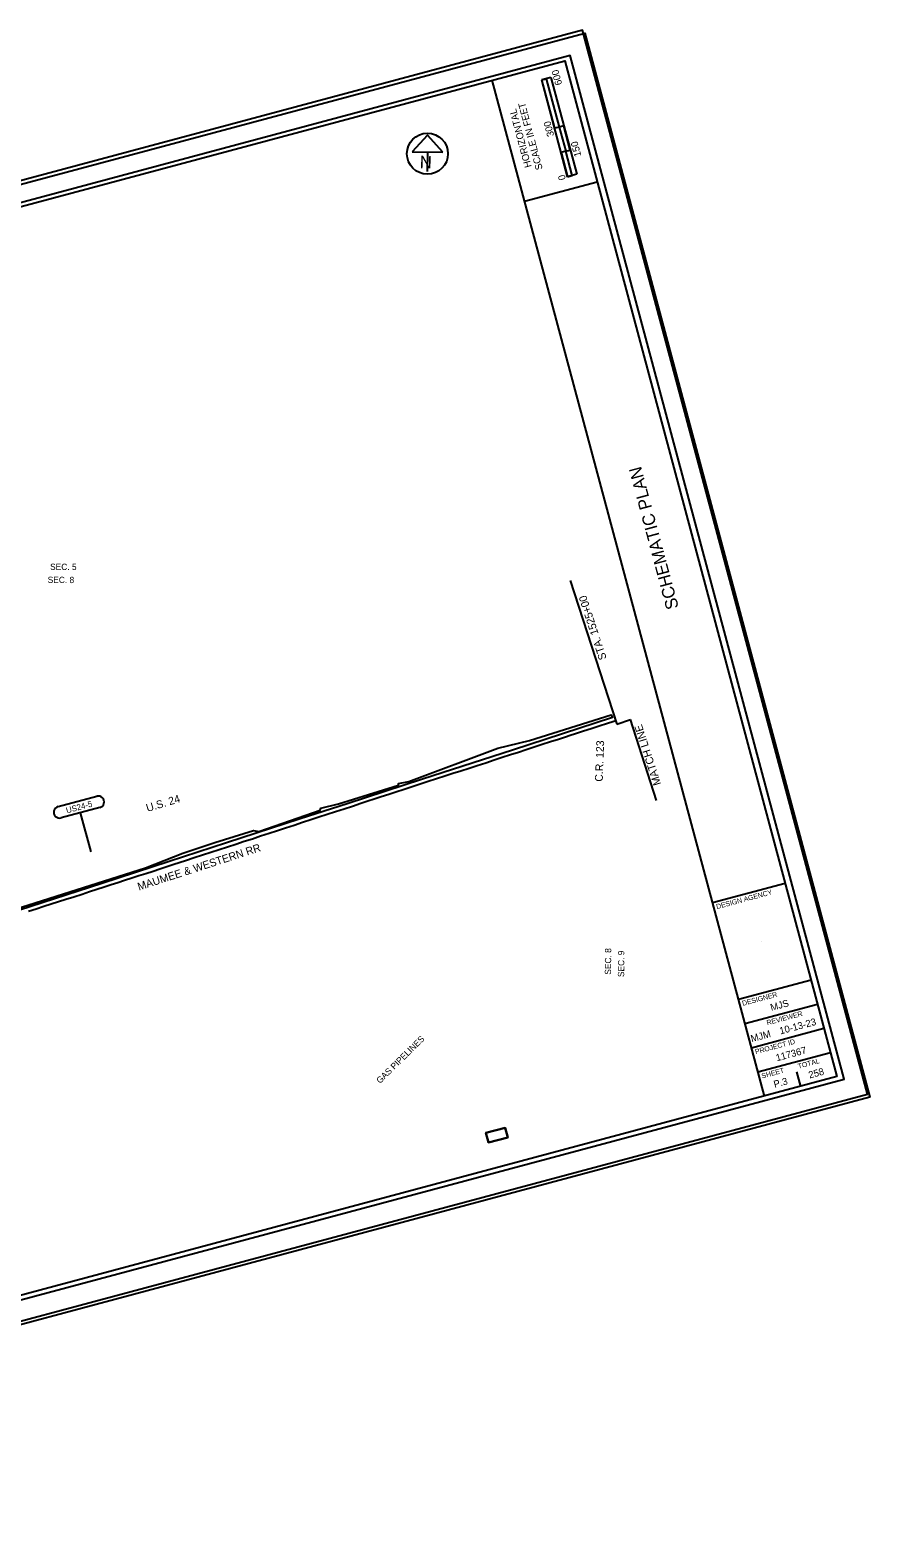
# Model space of a CAD drawing. Extents: x -361782439 to 1410642, y -263199455 to 583641.
# Drawn here: x 1405611 to 1410642, y 573245 to 582277 of the extents above; entities that cross this region are included whole.
import ezdxf

# ---------------------------------------------------------------- set-up
doc = ezdxf.new("R2010")
doc.units = 0
for name, color, linetype in [('HY_X_Wetland_Area', 7, 'Continuous'), ('Level 63', 7, 'Continuous'), ('RD_X_RR_1', 7, 'Continuous'), ('SH_Border', 7, 'Continuous'), ('SH_Cut_Line', 7, 'Continuous'), ('SH_Data', 7, 'Continuous'), ('SH_Masking', 7, 'Continuous'), ('SH_Text', 7, 'Continuous'), ('UT_X_Gas', 7, 'Continuous')]:
    doc.layers.add(name, color=color, linetype=linetype)

msp = doc.modelspace()

# ---------------------------------------------------------------- linework, layer by layer
at = {"layer": 'HY_X_Wetland_Area'}
msp.add_lwpolyline([(1404814.3, 576788.2), (1406301.7, 577259.9), (1406525.2, 577347.2), (1406717.1, 577411.1), (1406950.3, 577483.5), (1406982, 577477.5), (1407349, 577603.6), (1407353.2, 577617.4), (1407457.8, 577642.5), (1407818.3, 577753.7), (1407817.8, 577764.5), (1407879.3, 577776.4), (1407879.3, 577776.4), (1407879.3, 577776.4), (1408413.7, 577975.5), (1408603.3, 578020.9), (1409091.1, 578175.2), (1409100.6, 578159), (1408500.2, 577964.2), (1407961.4, 577789.4), (1407509.6, 577642.8), (1407229.4, 577552), (1406965.2, 577466.2), (1406787.2, 577408.5), (1406444.9, 577297.4), (1406444.9, 577297.4), (1406444.9, 577297.4), (1406040.1, 577166.1), (1404694.7, 576729.6)], dxfattribs=at)
for points in [[(1408341.6, 575671.3), (1408341.6, 575671.3), (1408341.6, 575671.3), (1408341.6, 575671.3), (1408341.6, 575671.3), (1408341.6, 575671.3), (1408457.5, 575702.4), (1408457.5, 575702.4), (1408473, 575644.4), (1408473, 575644.4), (1408473, 575644.4), (1408357.1, 575613.4), (1408357.1, 575613.4), (1408357.1, 575613.4), (1408357.1, 575613.4), (1408357.1, 575613.4), (1408357.1, 575613.4), (1408357.1, 575613.4), (1408357.1, 575613.4), (1408357.1, 575613.4), (1408341.6, 575671.3), (1408341.6, 575671.3)], [(1408341.6, 575671.3), (1408357.1, 575613.4), (1408473, 575644.4), (1408457.5, 575702.4)]]:
    msp.add_lwpolyline(points, close=True, dxfattribs=at)
at = {"layer": 'Level 63'}
for points in [[(1399081.8, 579619.5), (1408933.5, 582259.3), (1410641.6, 575884.9), (1400789.8, 573245.2)], [(1400867.8, 573415.1), (1410488.4, 575993), (1408845.4, 582124.7), (1399224.8, 579546.8)]]:
    msp.add_lwpolyline(points, close=True, dxfattribs=at)
at = {"layer": 'RD_X_RR_1'}
for points in [[(1409119.8, 578139.7), (1409102.2, 578134), (1409069.5, 578123.7), (1409019.3, 578107.4), (1408971.7, 578092.1), (1408926.3, 578077.5), (1408878.7, 578062.1), (1408847.3, 578051.8), (1408817.9, 578042.1), (1408775.5, 578028.5), (1408728.3, 578013.1), (1408679.4, 577997.4), (1408630.4, 577981.4), (1408582.6, 577965.9), (1408536.3, 577950.8), (1408488, 577935.2), (1408439.4, 577919.3), (1408391.3, 577903.4), (1408340.3, 577887), (1408290.1, 577870.7), (1408240.3, 577854.6), (1408192.3, 577838.9), (1408143.6, 577823.4), (1408095.2, 577807.6), (1408045.9, 577791.4), (1407996.4, 577775.7), (1407947.2, 577759.6), (1407900.2, 577744.4), (1407851.6, 577728.7), (1407802.7, 577712.6), (1407760, 577698.6), (1407714.5, 577683.6), (1407665.6, 577667.8), (1407640.8, 577659.5), (1407592.6, 577643.9), (1407542.1, 577627.4), (1407491.6, 577610.9), (1407440.7, 577594.3), (1407391.4, 577578.3), (1407341.6, 577562.1), (1407292.7, 577546.4), (1407242.1, 577529.8), (1407192.4, 577513.5), (1407142, 577496.9), (1407093.1, 577480.9), (1407042.5, 577464.4)], [(1407042.5, 577464.4), (1406991.9, 577447.8), (1406942.9, 577431.7), (1406894.3, 577415.8), (1406843.8, 577399.4), (1406793.9, 577383.2), (1406744.1, 577367.1), (1406694.2, 577350.8), (1406644.2, 577334.4), (1406593.8, 577318.2), (1406541.1, 577301.1), (1406472.6, 577278.9), (1406430.1, 577265), (1406388.2, 577251), (1406347.5, 577237.8), (1406304.3, 577223.9), (1406263.1, 577210.3), (1406219.9, 577196.5), (1406177.4, 577182.8), (1406137, 577169.7), (1406097, 577156.9), (1406055.3, 577143.6), (1406011.1, 577129), (1405966.9, 577114.7), (1405922.7, 577100.2), (1405872.3, 577083.7), (1405825, 577068.8), (1405780.5, 577054.5), (1405738.2, 577041.1), (1405693.6, 577026.6), (1405647.2, 577011.9), (1405601.4, 576997.3)]]:
    msp.add_lwpolyline(points, dxfattribs=at)
at = {"layer": 'SH_Border'}
for p, q in [((1410009.9, 575891.8), (1408379.3, 581977.1)), ((1408573.4, 581252.7), (1409008.1, 581369.2)), ((1409699.3, 577050.9), (1410133.9, 577167.4)), ((1409854.6, 576471.4), (1410289.2, 576587.8)), ((1409893.4, 576326.5), (1410328.1, 576442.9)), ((1409932.2, 576181.6), (1410366.9, 576298)), ((1409971, 576036.7), (1410405.7, 576153.2))]:
    msp.add_line(p, q, dxfattribs=at)
msp.add_lwpolyline([(1399541.1, 579608.9), (1408814, 582093.6), (1410444.5, 576008.3), (1401171.6, 573523.6)], close=True, dxfattribs=at)
at = {"layer": 'SH_Cut_Line'}
msp.add_lwpolyline([(1400775.8, 573262.3), (1410628.2, 575902.2), (1408920, 582277.3), (1399067.6, 579637.4)], close=True, dxfattribs=at)
at = {"layer": 'SH_Data'}
for p, q in [((1408730.3, 581993.5), (1408675.9, 581979)), ((1408675.9, 581979), (1408703, 581986.2)), ((1408831.2, 581399.4), (1408675.9, 581979)), ((1408753.6, 581689.2), (1408675.9, 581979)), ((1408703, 581986.2), (1408703.2, 581986.3)), ((1408703.2, 581986.3), (1408780.9, 581696.5)), ((1408730.3, 581993.5), (1408885.6, 581414)), ((1408780.9, 581696.5), (1408753.6, 581689.2)), ((1408807.7, 581703.7), (1408780.6, 581696.4)), ((1408780.6, 581696.4), (1408819.4, 581551.6)), ((1408846.5, 581558.8), (1408807.7, 581703.7)), ((1408819.4, 581551.6), (1408792.4, 581544.3)), ((1408792.4, 581544.3), (1408831.2, 581399.4)), ((1408819.4, 581551.6), (1408846.5, 581558.8)), ((1408858.3, 581406.7), (1408819.4, 581551.6)), ((1408885.6, 581414), (1408831.2, 581399.4)), ((1408831.2, 581399.4), (1408858.3, 581406.7)), ((1409994.3, 576819.4), (1409994.3, 576819.4)), ((1410227.2, 575950), (1410203.9, 576037)), ((1410104.9, 575971.6), (1410104.9, 575971.6))]:
    msp.add_line(p, q, dxfattribs=at)
at = {"layer": 'SH_Masking'}
msp.add_circle((1407991.4, 581536.9), 123, dxfattribs=at)
at = {"layer": 'SH_Text'}
for p, q in [((1407992.6, 581649), (1407899.2, 581547.6)), ((1408083.8, 581545.7), (1407992.6, 581649)), ((1407899.2, 581547.6), (1408083.8, 581545.7)), ((1407991.5, 581546.6), (1407990.3, 581430.6)), ((1408847.3, 578980.3), (1409126.4, 578120.6)), ((1409126.4, 578120.6), (1409206.9, 578146.7)), ((1409363.9, 577663.1), (1409206.9, 578146.7)), ((1405778.9, 577625.7), (1406010.7, 577687.8)), ((1406028.8, 577620.2), (1405797, 577558.1)), ((1406028.8, 577620.2), (1406028.8, 577620.2)), ((1405977, 577355.4), (1405912.9, 577589.1))]:
    msp.add_line(p, q, dxfattribs=at)
msp.add_circle((1407991.4, 581536.9), 123, dxfattribs=at)
for centre, start, end in [((1405787.9, 577591.9), 105, 285.00042), ((1406019.8, 577654), 284.99958, 105)]:
    msp.add_arc(centre, 35, start, end, dxfattribs=at)

# ---------------------------------------------------------------- texts
at = {"layer": 'SH_Data'}
for s, height, rotation, p in [('600', 42, 105, (1408798.8, 581953.5)), ('HORIZONTAL', 42, 105, (1408615.7, 581459.8)), ('SCALE IN FEET', 42, 105, (1408682.3, 581446.2)), ('300', 42, 105, (1408750.9, 581645.6)), ('150', 42, 105, (1408913.7, 581524.7)), ('0', 42, 105, (1408820.8, 581384.6)), ('SCHEMATIC PLAN', 75, 105, (1409497.5, 578818.2)), ('DESIGN AGENCY', 30, 15, (1409725.4, 577011.3)), ('DESIGNER', 30, 15, (1409880.7, 576431.8)), ('MJS', 42, 15, (1410051.5, 576401.5)), ('REVIEWER', 30, 15, (1410027.3, 576315.8)), ('10-13-23', 42, 15, (1410106.3, 576260.8)), ('MJM', 42, 15, (1409934.3, 576214.8)), ('PROJECT ID', 30, 15, (1409958.3, 576142)), ('117367', 42, 15, (1410084.5, 576099.7)), ('TOTAL', 30, 15, (1410214.5, 576055.3)), ('SHEET', 30, 15, (1409997.2, 575997.1)), ('P.3', 42, 15, (1410071.5, 575940.9)), ('258', 42, 15, (1410280.4, 575996.9))]:
    msp.add_text(s, height=height, rotation=rotation, dxfattribs=at).set_placement(p)
at = {"layer": 'SH_Text'}
for s, height, rotation, p in [('N', 75, 359.40814, (1407945.1, 581450)), ('SEC. 5', 37.5, 359.57918, (1405730.6, 579044.1)), ('SEC. 8', 37.5, 359.57918, (1405716.2, 578965.9)), ('STA. 1525+00', 46.8, 107.98637, (1409065.6, 578513.1)), ('MATCH LINE', 46.8, 107.98637, (1409391.7, 577761.3)), ('C.R. 123', 46.8, 87.922, (1409041.1, 577774.4)), ('US24-5', 35.5, 15, (1405831.5, 577585.1)), ('U.S. 24', 46.8, 16.64762, (1406314, 577593.7)), ('MAUMEE & WESTERN RR', 46.8, 17.97385, (1406263.1, 577122.6)), ('SEC. 8', 37.5, 89.57918, (1409091.3, 576618.7)), ('SEC. 9', 37.5, 89.57918, (1409169.6, 576604.3))]:
    msp.add_text(s, height=height, rotation=rotation, dxfattribs=at).set_placement(p)
at = {"layer": 'UT_X_Gas'}
msp.add_text('GAS PIPELINES', height=37.5, rotation=44.63239, dxfattribs=at).set_placement((1407707.3, 575963.8))

doc.saveas('drawing.dxf')
